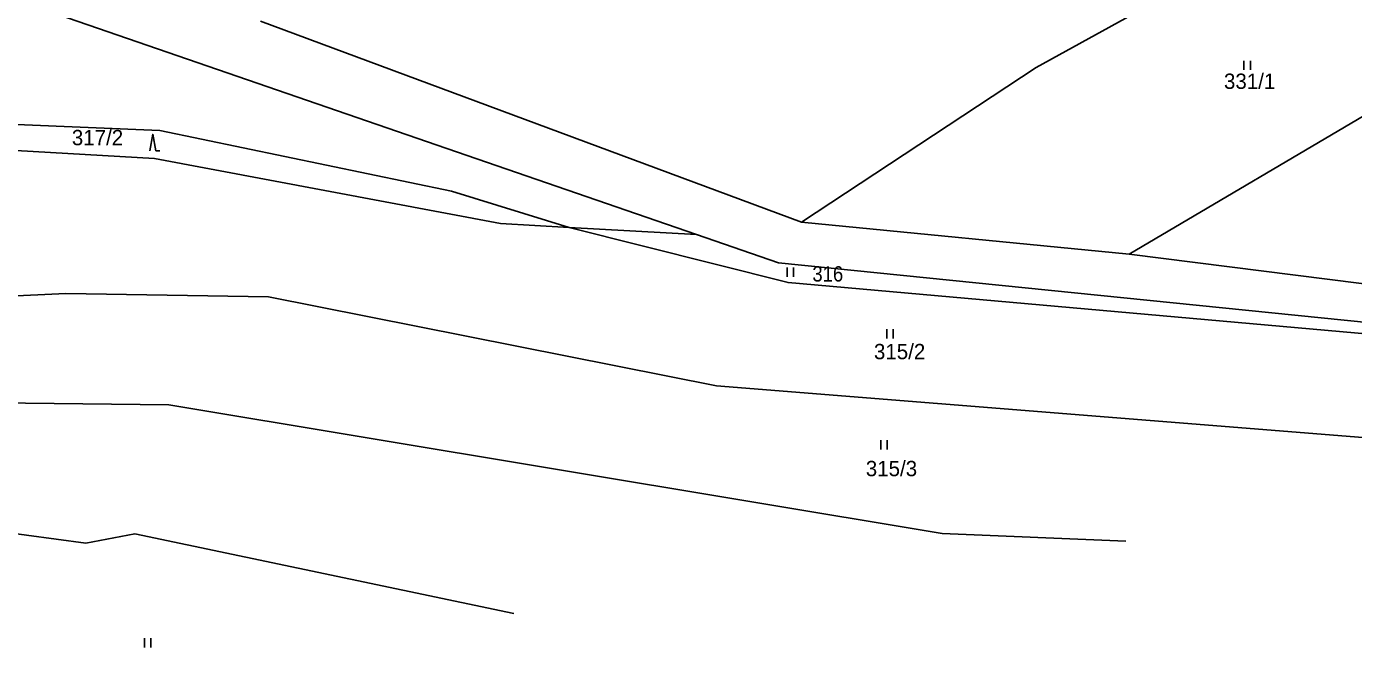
# Model space of a CAD drawing. Extents: x -680102 to -677253, y -1007548 to -1006096.
# Drawn here: x -679518.8 to -679302.6, y -1007492 to -1007390.7 of the extents above; entities that cross this region are included whole.
import ezdxf
from ezdxf.enums import TextEntityAlignment as Align

# ---------------------------------------------------------------- set-up
doc = ezdxf.new("R2010")
doc.units = 0
doc.layers.add('1', color=7, linetype='Continuous', lineweight=25)
doc.layers.add('25', color=7, linetype='Continuous', lineweight=25)
doc.layers.add('18', color=7, linetype='Continuous')

msp = doc.modelspace()

# ---------------------------------------------------------------- linework, layer by layer
at = {"layer": '1'}
for p, q in [((-679480.71, -1007389.87), (-679392.55, -1007422.66)), ((-679339.14, -1007427.85), (-679277.62, -1007391.57)), ((-679449.59, -1007417.57), (-679430.42, -1007423.5)), ((-679392.55, -1007422.66), (-679339.14, -1007427.85)), ((-679495.67, -1007452.42), (-679564.37, -1007451.65)), ((-679535.19, -1007471.47), (-679509.2, -1007475))]:
    msp.add_line(p, q, dxfattribs=at)
for points in [[(-679392.55, -1007422.66), (-679354.27, -1007397.43), (-679302.19, -1007368.68)], [(-679557.5, -1007373.16), (-679549.86, -1007376.28), (-679549.6, -1007376.39), (-679409.65, -1007424.66), (-679396.29, -1007429.27), (-679283.7, -1007440.7), (-679277.3, -1007443.79), (-679273.41, -1007446.8)], [(-679543.91, -1007405.75), (-679497.1, -1007407.72), (-679449.59, -1007417.57)], [(-679548, -1007409.36), (-679497.99, -1007412.27), (-679441.58, -1007422.87)], [(-679441.58, -1007422.87), (-679430.42, -1007423.5), (-679409.65, -1007424.66)], [(-679430.42, -1007423.5), (-679394.73, -1007432.51), (-679285.28, -1007442.24), (-679274.03, -1007447.06)], [(-679339.14, -1007427.85), (-679274.14, -1007436.07), (-679268.25, -1007440.13)], [(-679299.68, -1007457.86), (-679406.38, -1007449.32), (-679479.4, -1007434.83), (-679512.45, -1007434.27), (-679564.1, -1007436.71)], [(-679495.67, -1007452.42), (-679369.63, -1007473.44), (-679339.66, -1007474.68)], [(-679509.2, -1007475), (-679501.19, -1007473.5), (-679439.42, -1007486.5)]]:
    msp.add_lwpolyline(points, dxfattribs=at)
at = {"layer": '25'}
for p, q in [((-679320.417, -1007397.825), (-679320.417, -1007396.325)), ((-679319.383, -1007397.825), (-679319.383, -1007396.325)), ((-679394.877, -1007431.555), (-679394.877, -1007430.055)), ((-679393.843, -1007431.555), (-679393.843, -1007430.055)), ((-679378.627, -1007441.605), (-679378.627, -1007440.105)), ((-679377.593, -1007441.605), (-679377.593, -1007440.105)), ((-679379.627, -1007459.705), (-679379.627, -1007458.205)), ((-679378.593, -1007459.705), (-679378.593, -1007458.205)), ((-679499.597, -1007492.015), (-679499.597, -1007490.515)), ((-679498.563, -1007492.015), (-679498.563, -1007490.515))]:
    msp.add_line(p, q, dxfattribs=at)
msp.add_lwpolyline([(-679498.772, -1007411), (-679498.27, -1007408.319), (-679497.767, -1007411), (-679497.097, -1007411)], dxfattribs=at)

# ---------------------------------------------------------------- texts
at = {"layer": '18'}
for s, p in [('331/1', (-679319.5, -1007400.91)), ('317/2', (-679507.28, -1007410.1))]:
    msp.add_text(s, height=2.5, dxfattribs=at).set_placement(p, align=Align.CENTER)
at = {"layer": '18', "width": 0.9}
msp.add_text('316', height=2.5, dxfattribs=at).set_placement((-679388.25, -1007432.33), align=Align.CENTER)
at = {"layer": '18'}
for s, p in [('315/2', (-679380.73, -1007445)), ('315/3', (-679382.06, -1007464.08))]:
    msp.add_text(s, height=2.5, dxfattribs=at).set_placement(p)

doc.saveas('drawing.dxf')
